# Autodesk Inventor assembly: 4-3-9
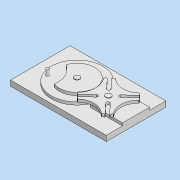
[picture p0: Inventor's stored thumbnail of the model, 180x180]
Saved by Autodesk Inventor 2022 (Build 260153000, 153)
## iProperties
Created: 2021-07
Part Number: 4-3-9
Document SubType Name: Assembly
Designer: DesignLab
Author: DesignLab
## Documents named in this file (5)
- d:\Users\DesignLab\Desktop\ver2022\ch04\4-3-9.iam
- d:\Users\DesignLab\Desktop\ver2022\ch04\03-ベース板_完成.ipt
- d:\Users\DesignLab\Desktop\ver2022\ch04\01-駆動車_完成.ipt
- d:\Users\DesignLab\Desktop\ver2022\ch04\02-従動車_完成.ipt
- d:\Users\DesignLab\Desktop\ver2022\ch04\04-ピン_完成.ipt
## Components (5 placed, 4 different names)
1. 03-ベース板_完成:1 — 回転:1, 回転:2
2. 01-駆動車_完成:1 — 回転:1, フラッシュ:1
3. 02-従動車_完成:1 — 回転:2, 回転:3
4. 04-ピン_完成:1 — フラッシュ:1
5. 04-ピン_完成:2 — 回転:3
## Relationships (4: RevoluteJoint 3, Flush 1)
- 回転:1 [RevoluteJoint]: 03-ベース板_完成:1 ↔ 01-駆動車_完成:1
- 回転:2 [RevoluteJoint]: 03-ベース板_完成:1 ↔ 02-従動車_完成:1
- フラッシュ:1 [Flush]: 01-駆動車_完成:1 ↔ 04-ピン_完成:1
- 回転:3 [RevoluteJoint]: 02-従動車_完成:1 ↔ 04-ピン_完成:2
